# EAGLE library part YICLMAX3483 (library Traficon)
3.3V Powered, 10Mbps and Slew-Rate Limited, True RS-485/RS-422 Transceivers
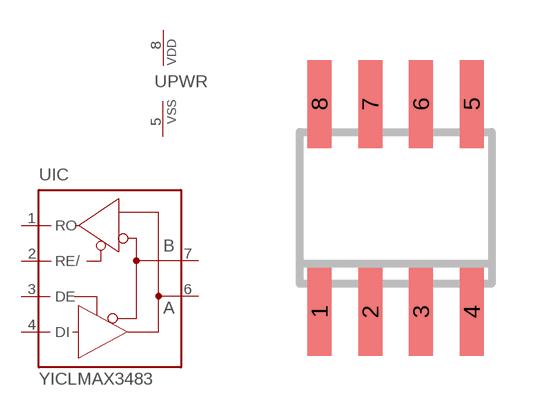
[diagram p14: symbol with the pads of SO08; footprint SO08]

Designator prefix U; gates IC=MAX481 PWR=3V3-GND

## YICLMAX3483  [SO08]
1  IC:RO  out
2  IC:RE/  in
3  IC:DE  in
4  IC:DI  in
5  PWR:VSS  pwr
6  IC:A  pas
7  IC:B  pas
8  PWR:VDD  pwr

## Footprint SO08 (pad centres in mm)
Small Outline Package
smd 0.6 x 2.2: 1 -1.905,-2.6; 2 -0.635,-2.6; 3 0.635,-2.6; 4 1.905,-2.6; 5 1.905,2.6; 6 0.635,2.6; 7 -0.635,2.6; 8 -1.905,2.6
